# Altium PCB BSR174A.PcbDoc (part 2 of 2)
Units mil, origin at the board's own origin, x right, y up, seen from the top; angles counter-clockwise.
Board outline 4000 x 3000 mil, 6 copper layers (Top Layer, Signal Layer 1, Signal Layer 2, Signal Layer 3, Signal Layer 4, Bottom Layer), stack 61.8 mil thick; 80 components, 28 nets, 166 pads, 381 vias.
Unrouted connection lines stored in the file: 48.
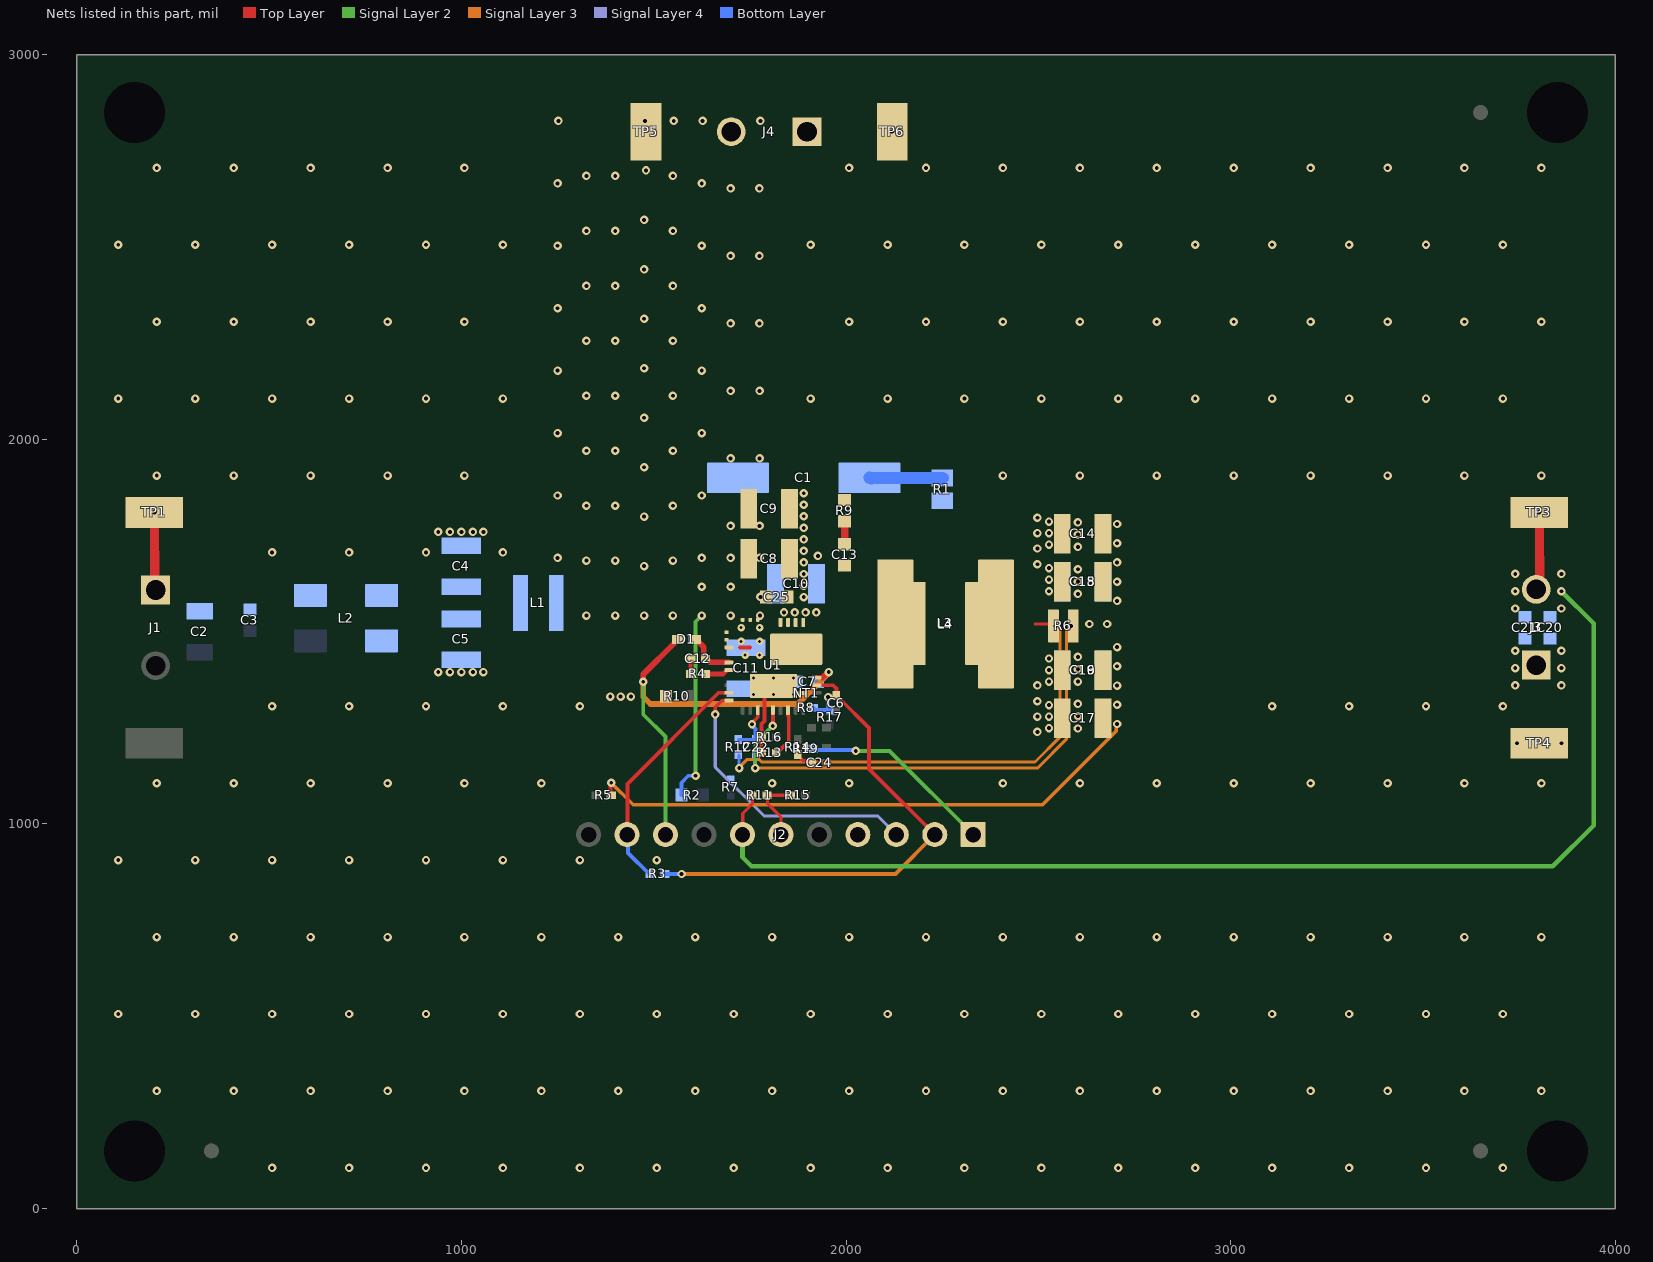
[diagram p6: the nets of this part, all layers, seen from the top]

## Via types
v1: diameter 22, hole 10, Top Layer to Bottom Layer, tented both sides, 364 vias
v2: diameter 19.68, hole 7.87, Top Layer to Bottom Layer, 12 vias
v3: diameter 22, hole 10, Top Layer to Bottom Layer, 5 vias

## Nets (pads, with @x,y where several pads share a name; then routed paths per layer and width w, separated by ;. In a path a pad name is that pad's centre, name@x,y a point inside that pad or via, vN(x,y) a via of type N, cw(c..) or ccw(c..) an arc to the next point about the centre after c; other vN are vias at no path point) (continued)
GND: C4.2 C5.2 C7.2 C8.2 C9.2 C10.2 C11.2 C14.2 C15.2 C16.2 C17.2 C18.2 C19.2 C20.2 C21.2 C25.2 J2.4 J3.1 J4.1 L2.2 NT1.1 R1.1 R7.1 R9.2 R10.1 R13.2 R16.1 TP4.1 TP6.1 U1.23 U1.24 U1.25 U1.26 U1.30 | length 199.3
  Top Layer w6: U1.30@1819.18,1343.22 U1.30@1828.28,1352.32
  Top Layer w10: R13.2@1780.31,1185 1780.32,1259.61 1788.5,1267.8 1788.5,1335.55 U1.30@1811.46,1358.5
  other v1: 508,106 708,106 908,106 1108,106 1308,106 1508,106 1708,106 1908,106 2108,106 2308,106 2508,106 2708,106 2908,106 3108,106 3308,106 3508,106 3708,106 208,306 408,306 608,306 808,306 1008,306 1208,306 1408,306 1608,306 1808,306 2008,306 2208,306 2408,306 2608,306 2808,306 3008,306 3208,306 3408,306 3608,306 3808,306 108,506 308,506 508,506 708,506 908,506 1108,506 1308,506 1508,506 1708,506 1908,506 2108,506 2308,506 2508,506 2708,506 2908,506 3108,506 3308,506 3508,506 3708,506 208,706 408,706 608,706 808,706 1008,706 1208,706 1408,706 1608,706 1808,706 2008,706 2208,706 2408,706 2608,706 2808,706 3008,706 3208,706 3408,706 3608,706 3808,706 108,906 308,906 508,906 708,906 908,906 1108,906 1308,906 1508,906 208,1106 408,1106 608,1106 808,1106 1008,1106 1208,1106 1808,1106 2008,1106 2408,1106 2608,1106 2808,1106 3008,1106 3208,1106 3408,1106 3608,1106 3808,1106 2497.81,1239.34 2602.81,1248.34 2527.81,1249.34 2497.81,1279.34 2527.81,1279.34 2603.2,1280.34 508,1306 708,1306 908,1306 1108,1306 1308,1306 3108,1306 3308,1306 3508,1306 3708,1306 2527.81,1309.34 2602.81,1312.34 2497.81,1319.34 1386.95,1331.4 1413.95,1331.4 1440.95,1331.4 2497.81,1360.34 3740,1360.34 3860,1360.34 2527.81,1370.34 2602.81,1370.34 940,1395 970,1395 1000,1395 1030,1395 1057.24,1395 2527.81,1400.34 2602.81,1402.34 3740,1405.34 3860,1405.34 2527.81,1430.34 2602.81,1434.34 3740,1450.34 3860,1450.34 1838.81,1550.34 1866.81,1550.34 1894.81,1550.34 1922.81,1550.34 1890,1590 2602.81,1598.36 2527.81,1605.34 1890,1620 2602.81,1630.35 2527.81,1635.34 1890,1650 2602.81,1662.34 2527.81,1665.34 2497.81,1675.34 1890,1680 1926.87,1697.24 508,1706 708,1706 908,1706 1108,1706 1890,1710 2497.81,1716.34 2602.81,1720.34 2527.81,1726.34 1890,1740 2602.81,1752.34 2497.81,1756.34 2527.81,1756.34 940,1759.3 970,1759.3 1000,1759.3 1030,1759.3 1057.24,1759.3 1890,1770 2602.81,1784.34 2527.81,1786.34 2497.81,1796.34 1890,1800 1890,1830 1890,1860 208,1906 408,1906 608,1906 808,1906 1008,1906 2408,1906 2608,1906 2808,1906 3008,1906 3208,1906 3408,1906 3608,1906 3808,1906 108,2106 308,2106 508,2106 708,2106 908,2106 1108,2106 1908,2106 2108,2106 2308,2106 2508,2106 2708,2106 2908,2106 3108,2106 3308,2106 3508,2106 3708,2106 208,2306 408,2306 608,2306 808,2306 1008,2306 2008,2306 2208,2306 2408,2306 2608,2306 2808,2306 3008,2306 3208,2306 3408,2306 3608,2306 3808,2306 108,2506 308,2506 508,2506 708,2506 908,2506 1108,2506 1908,2506 2108,2506 2308,2506 2508,2506 2708,2506 2908,2506 3108,2506 3308,2506 3508,2506 3708,2506 208,2706 408,2706 608,2706 808,2706 1008,2706 2008,2706 2208,2706 2408,2706 2608,2706 2808,2706 3008,2706 3208,2706 3408,2706 3608,2706 3808,2706 2120,2800
  other v2: 1759.8,1337.17 1811.46,1337.17 1863.15,1337.17 1759.8,1379.84 1811.46,1379.84 1863.15,1379.84
  other v3: 3745,1210 3860,1210
ISNS+: C22.2 R12.1 U1.11 | length 128.5
  Top Layer w10: v1(1755.57,1259.34) 1755.57,1262.59 1770.55,1277.58 1770.55,1295.75 U1.11@1770.63,1295.83
  Bottom Layer w10: R12.1@1721.46,1218.92 C22.2@1763.71,1218.92 ; v1(1755.57,1259.34) 1755.57,1256.1 1765,1246.66 C22.2@1765,1219.69
NetC1_2: C1.2 R1.2 | length 191.1
  Bottom Layer w32: C1.2@2061.26,1900 2061.5,1899.76 2250.37,1899.76 2250.97,1899.17 R1.2@2251.32,1899.53 ; C1.2@2066.07,1898.82 C1.2@2066.43,1899.17
NetC2_1: C2.1 C3.1 J1.1 L2.4 TP1.1 | length 201.2
  Top Layer w24: v3(202,1810) J1.1@202.81,1608.77
NetC4_1: C4.1 C5.1 L1.1 L2.1
NetC12_1: C12.1 D1.1 U1.4 | length 130.4
  Top Layer w12: U1.4@1695.22,1420.45 U1.4@1695.83,1419.84
  Top Layer w15: D1.1@1606.65,1480 1610.59,1480 1630.37,1460.22 1630.37,1432.34 1632.72,1430 C12.1@1634.68,1430 1636.65,1430 1646.2,1420.45 U1.4@1695.22,1420.45
NetC12_2: C12.2 R4.2 | length 40
  Top Layer w10: R4.2@1595.31,1390 C12.2@1595.31,1430
NetC13_2: C13.2 R9.1 | length 59.9
  Top Layer w20: C13.2@1996.45,1727.2 R9.1@1996.45,1787.13
NetC24_1: C24.1 R14.1 | length 41.7
  Top Layer w10: R14.1@1875.89,1177.46 1888.8,1164.55 1905.77,1164.55 C24.1@1910.32,1160
NetJ2_1: J2.1 R19.1 | length 511.2
  Top Layer w10: J2.1@2330.5,972.66 J2.1@2330.81,972.34
  Signal Layer 2 w10: v1(2025.16,1190) 2113.16,1190 J2.1@2330.81,972.34
  Bottom Layer w10: R19.1@1914.68,1199.84 1914.68,1199.11 1921.5,1192.3 2022.86,1192.3 v1(2025.16,1190)
NetL3_2: L3.2 L4.2 R6.1 R12.2 | length 1242.3
  Top Layer w8: v1@1721.46,1146.27 v1(1722.38,1145.34) ; 2492.03,1520.34 R6.1@2530,1520.42
  Signal Layer 3 w8: v1(1722.38,1145.34) 1722.38,1147.42 1743.19,1168.22 1773.59,1168.22 1780.59,1161.22 2491.25,1161.22 2556.94,1226.91 2556.94,1503.06 v1(2545,1515)
  Bottom Layer w8: R12.2@1721.46,1179.55 1721.46,1146.27 v1(1722.38,1145.34)
PFMSYNC: J2.3 U1.8 | length 742.4
  Top Layer w8: v1(1660,1285) 1660,1303.48 1677.94,1321.42 U1.8@1695.83,1321.42
  Signal Layer 4 w8: v1(1660,1285) 1660,1147.81 1786.74,1021.07 2082.08,1021.07 J2.3@2130.81,972.34
PGSYNC: J2.10 R3.1 U1.7 | length 622.2
  Top Layer w10: J2.10@1431.53,972.34 1431.53,1103.91 1668.73,1341.1 U1.7@1695.83,1341.1
  Bottom Layer w10: J2.10@1430.81,972.34 1433.48,969.68 1433.48,924.86 1488.35,870 R3.1@1490.32,870
RT: R13.1 U1.14 | length 121.3
  Top Layer w10: R13.1@1822.83,1187.44 1825.58,1190.19 1826.16,1190.19 1851.26,1215.29 1851.26,1280.76 1849.45,1282.57 1849.45,1295.75 U1.14@1849.37,1295.83
SW: C13.1 L3.1 L4.1 U1. U1.20 U1.21 U1.22
SW1: R4.1 U1.5 | length 59.1
  Top Layer w12: R4.1@1634.68,1390 1680.94,1390 U1.5@1690.02,1399.08
VBODE: J2.6 R11.1 R15.2 | length 195.1
  Top Layer w8: J2.6@1849.53,972.34 1831.53,972.34 1831.53,1017.34 1796.22,1052.66 1796.22,1074.79 R15.2@1856.2,1074.79
VCC: C7.1 D1.2 J2.9 U1.19 | length 1224.6
  Top Layer w12: U1.19@1924.86,1381.16 1939.12,1381.16
  Top Layer w15: v1(1472.96,1369.98) 1472.96,1389.62 1555.1,1471.75 1555.1,1475.69 1559.41,1480 D1.2@1563.35,1480 ; 1939.12,1381.16 1939.81,1381.16 1953.65,1395 v1(1955,1395)
  Signal Layer 2 w10: v1(1472.96,1369.98) 1472.96,1285.1 1530.49,1227.57 J2.9@1530.49,973.39
  Signal Layer 3 w15: v1(1472.96,1369.98) 1472.96,1330.5 1491.51,1311.95 1874.78,1311.95 1951.5,1388.67 1951.5,1389.61 1955,1393.11 v1(1955,1395)
  Bottom Layer w15: C7.1@1933.62,1362.23 1925.37,1370.47 1925.37,1371.59 1933.62,1379.84 1941.81,1379.84 1941.81,1380.46 1955,1393.65 v1(1955,1395)
VDDA: C6.2 J2.2 R3.2 R8.2 R17.2 U1.18 | length 1379.2
  Top Layer w10: U1.18@1924.25,1360.71 U1.18@1924.17,1360.79 1966.53,1360.79 1975,1352.32 C6.2@1975,1333.68 1973.16,1331.84 1955.19,1331.84 v1(1953.35,1330) ; C6.2@1975,1331.71 1979.84,1326.87 1982.3,1326.87 2060,1249.17 2060,1143.16 J2.2@2230.81,972.34
  Signal Layer 3 w10: v1(1572.44,870) 2128.47,870 J2.2@2230.81,972.34
  Bottom Layer w10: R3.2@1529.69,870 v1(1572.44,870) ; R8.2@1915.94,1301.73 1920.78,1296.89 1928.38,1296.89 1928.61,1296.66 R17.2@1958.21,1296.66 ; R17.2@1953.37,1301.73 1953.37,1309.3 ; 1953.35,1309.33 v1(1953.35,1330)
VIN: C1.1 C8.1 C9.1 C10.1 C11.1 C25.1 J4.2 L1.2 R2.2 TP5.1 U1.1 U1.2 U1.3 U1.27 U1.28 U1.29 | length 525.6
  Top Layer w10: 1724.38,1459.17 1750.33,1459.17
  Signal Layer 2 w10: v1(1608.97,1125.34) 1608.97,1525.82 v1(1625,1541.85)
  Bottom Layer w10: R2.2@1571.94,1075.34 1571.94,1107.31 1589.97,1125.34 v1(1608.97,1125.34)
  other v1: 1325,1541.85 1400,1541.85 1475,1541.85 1550,1541.85 1700,1541.85 1776.43,1541.85 1777.33,1590.59 1625,1616.85 1700,1616.85 1475,1670.45 1325,1684.74 1400,1684.74 1550,1684.74 1250,1691.85 1625,1691.85 1700,1691.85 1775.4,1691.85 1700,1775 1775.4,1775 1475,1799.06 1325,1827.64 1400,1827.64 1550,1827.64 1250,1854.14 1625,1854.14 1475,1927.66 1700,1950.48 1775.4,1950.48 1325,1970.53 1400,1970.53 1550,1970.53 1250,2016.43 1625,2016.43 1475,2056.27 1325,2113.43 1400,2113.43 1550,2113.43 1700,2125.97 1775.4,2125.97 1250,2178.73 1625,2178.73 1475,2184.87 1325,2256.32 1400,2256.32 1550,2256.32 1700,2301.45 1775,2301.45 1475,2313.48 1250,2341.02 1625,2341.02 1325,2399.21 1400,2399.21 1550,2399.21 1475,2442.08 1700,2476.93 1775,2476.93 1250,2503.31 1625,2503.31 1325,2542.11 1400,2542.11 1550,2542.11 1475,2570.69 1700,2652.41 1775,2652.41 1250,2665.6 1625,2665.6 1325,2685 1400,2685 1550,2685 1480,2699.29 1252.33,2827.9 1477.33,2827.9 1552.33,2827.9 1627.33,2827.9 1777.33,2827.9
  other v2: 1737.8,1438.9 1775.55,1438.9 1727.32,1474.65 1775.55,1474.65 1727.32,1510.39 1775.55,1510.39
VOUT: C14.1 C15.1 C16.1 C17.1 C18.1 C19.1 C20.1 C21.1 C22.1 J2.7 J3.2 R5.1 R6.2 R11.2 TP3.1 U1.12 | length 6107.1
  Top Layer w8: J2.7@1731.53,972.34 1731.53,1027.43 1756.85,1052.75 R11.2@1756.85,1074.79 ; TP3.1@3798.81,1789.34 TP3.1@3802.81,1785.34
  Top Layer w10: R5.1@1387.5,1075.4 1387.5,1105.38 v1(1389.47,1107.34) ; v1(1809.51,1255.05) 1809.92,1255.46 1809.92,1295.75 U1.12@1810,1295.83
  Top Layer w24: TP3.1@3802.81,1809.19 3802.89,1789.36 J3.2@3803.63,1605.15
  Signal Layer 2 w10: v1(1764.11,1145.34) 1764.11,1209.92 1809.24,1255.05 v1(1809.51,1255.05)
  Signal Layer 2 w12: J2.7@1730.81,972.34 1730.81,913.57 1754.39,890 3837.81,890 3944,996.19 3944,1521.34 v1(3860,1605.34)
  Signal Layer 3 w8: v1(1764.11,1145.34) 2497.83,1145.34 2572.81,1220.33 2572.81,1502.81 v1(2585,1515)
  Signal Layer 3 w10: v1(1389.47,1107.34) 1446.81,1050 2511.08,1050 2702.7,1241.62 2702.7,1257.7 v1(2705,1260) ; J2.7@1728.21,972.34 J2.7@1730.81,972.34
  Bottom Layer w8: v1(1764.11,1145.34) C22.1@1764.11,1179.96
  other v1: 2705,1310 2705,1360 2705,1410 2705,1460 2632.81,1520 2678.81,1520 3740,1560.34 3860,1560.34 2705,1580 3740,1605.34 2705,1630 3740,1650.34 3860,1650.34 2705,1680 2705,1730 2705,1780
  other v3: 3802,1810
pads on no net: FID1.1 FID2.1 FID3.1 FID4.1 FID5.1 FID6.1 MH1.1 MH2.1 MH3.1 MH4.1 U1.10

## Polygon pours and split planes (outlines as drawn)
SW on Top Layer "TOP_LAYER_SW_P3590" (solid, remove dead copper, pour order 3590): 1926.32,1410.61 1921.94,1406.23 cw(c1918.54,1409.62) 1918.54,1404.82 1806.18,1404.82 cw(c1806.18,1411.58) 1799.42,1411.58 1799.42,1492.75 cw(c1807.66,1492.76) 1807.68,1500.99 1909.15,1500.77 ccw(c1909.2,1522.43) 1924.5,1507.1 1965.25,1547.76 ccw(c1948.18,1564.87) 1972.36,1564.88 1972.36,1683.25 cw(c1982.27,1683.25) 1982.27,1693.17 2196.12,1693.17 cw(c2196.12,1682.55) 2206.74,1682.55 2206.74,1357.89 cw(c2199.05,1357.89) 2199.05,1350.2 2080.26,1350.2 cw(c2080.26,1378.05) 2060.56,1358.35 2022.25,1396.67 ccw(c1982.89,1357.32) 1982.87,1412.98 1932.04,1412.98 ccw(c1932.03,1404.9)
VIN on Top Layer "TOP_LAYER_VIN_P3592" (solid, remove dead copper, pour order 3592): 1656.5,1438.1 1656.5,1464.14 ccw(c1615.1,1464.14) 1614.92,1505.54 1250.98,1504.04 cw(c1250.89,1524.93) 1230,1524.93 1230,2831.22 cw(c1272.44,2831.22) 1272.44,2873.66 1772.09,2873.66 cw(c1772.09,2831.22) 1814.53,2831.21 1814.54,1566.88 1805.89,1566.88 ccw(c1805.89,1549.14) 1788.15,1549.14 1788.15,1427.68 1666.91,1427.68 cw(c1666.91,1438.1)
NetL3_2 on Top Layer "TOP_LAYER_NETL3_2_P3589" (solid, remove dead copper, pour order 3589): 2436.89,1648.98 2436.89,1688.34 ccw(c2432.06,1688.34) 2432.06,1693.17 2317.5,1693.17 ccw(c2317.5,1685.67) 2310,1685.67 2310,1577.49 2310,1490.94 2310,1354.73 ccw(c2314.54,1354.73) 2314.54,1350.2 2437.27,1350.2 ccw(c2437.27,1355.02) 2442.1,1355.02 2442.1,1393.43 cw(c2493.12,1393.43) 2457.04,1429.51 2481.71,1454.18 cw(c2514.88,1421.02) 2514.88,1467.92 2555,1467.92 2555,1566.66 2513.85,1566.66 cw(c2513.85,1609.41) 2483.62,1579.18 2453.2,1609.59 cw(c2492.58,1648.98)
GND on Top Layer "TOP_LAYER_GND_P3593" (solid, pour order 3593): -0.49,0 -0.49,3000 4000,3000 4000,0
AGND on Top Layer "TOP_LAYER_AGND_P3588" (solid, remove dead copper, pour order 3588): 1906.11,1345.66 1935.98,1345.66 1935.98,1320.08 ccw(c1946.3,1320.08) 1946.3,1309.76 1980.15,1309.76 cw(c1980.15,1305.69) 1984.23,1305.67 1983.51,1159.8 cw(c1973.68,1159.83) 1973.67,1150 1940,1150 cw(c1939.99,1156.18) 1933.81,1156.19 1933.81,1260.89 1906.11,1288.6
VOUT on Top Layer "TOP_LAYER_VOUT_P3591" (solid, remove dead copper, pour order 3591): 2642.59,1797.63 2642.59,1579.17 cw(c2621.75,1579.17) 2621.75,1558.33 2574.94,1558.33 2574.94,1471.79 2624.96,1471.79 cw(c2624.96,1454.16) 2642.59,1454.15 2642.59,1224.08 ccw(c2671.37,1224.08) 2671.37,1195.31 2766.61,1195.31 ccw(c2766.61,1218.7) 2790,1218.7 2790,1441.56 cw(c2820.23,1441.56) 2820.23,1471.79 3974.78,1471.79 3974.78,1689.19 2813.6,1689.19 cw(c2813.6,1712.8) 2790,1712.8 2790,1788.59 ccw(c2761.07,1788.59) 2761.07,1817.52 2662.49,1817.52 ccw(c2662.49,1797.63)
VOUT on Bottom Layer "BOTTOM_LAYER_VOUT_P3607" (solid, remove dead copper, pour order 3607): 2638.33,1788.03 2638.33,1580.62 cw(c2625.67,1580.62) 2625.67,1567.96 2616.21,1567.96 ccw(c2616.21,1556.14) 2604.4,1556.14 2604.4,1472.01 ccw(c2614.22,1472.01) 2614.22,1462.19 2629.85,1462.19 cw(c2629.85,1453.71) 2638.33,1453.71 2638.33,1223.77 ccw(c2666.79,1223.77) 2666.79,1195.31 2764.16,1195.31 ccw(c2764.16,1224.41) 2793.26,1224.41 2793.26,1469 cw(c2831.45,1469) 2831.45,1507.2 3873.29,1507.2 ccw(c3873.29,1526.66) 3892.75,1526.66 3892.75,1669.75 ccw(c3873.94,1669.76) 3873.93,1688.57 2822.86,1688.57 cw(c2822.86,1718.17) 2793.26,1718.18 2793.26,1787 ccw(c2759.25,1787) 2759.25,1821.01 2671.32,1821.01 ccw(c2671.31,1788.03)
GND on Bottom Layer "BOTTOM_LAYER_GND_P3609" (solid, remove dead copper, pour order 3609): -7,0 -7,3000 4000,3000 4000,0
NetC2_1 on Bottom Layer "BOTTOM_LAYER_NETC2_1_P3604" (solid, remove dead copper, pour order 3604): 877.81,1550 330,1550 330,1634.53 877.81,1634.53
EMIGND on Bottom Layer "BOTTOM_LAYER_EMIGND_P3602" (solid, remove dead copper, pour order 3602): 624.14,1411.57 330,1411.57 330,1486.14 cw(c352.56,1486.14) 352.56,1508.7 650,1508.7 650,1437.43 cw(c624.14,1437.43)
NetC4_1 on Bottom Layer "BOTTOM_LAYER_NETC4_1_P3603" (solid, remove dead copper, pour order 3603): 746,1639.76 1169.93,1639.76 1169.93,1512.05 746,1512.05
EMIGND on Bottom Layer "BOTTOM_LAYER_EMIGND_P3605" (solid, remove dead copper, pour order 3605): 2.38,1490 321.02,1490 cw(c321.02,1453.2) 357.81,1453.2 357.81,1217.81 cw(c325.34,1217.81) 325.34,1185.34 2.38,1185.34
NetC2_1 on Bottom Layer "BOTTOM_LAYER_NETC2_1_P3606" (solid, remove dead copper, pour order 3606): 2.38,1514.51 315.23,1514.51 ccw(c315.23,1557.09) 357.81,1557.09 357.81,1808.23 ccw(c330.7,1808.23) 330.7,1835.34 2.38,1835.34
VIN on Bottom Layer "BOTTOM_LAYER_VIN_P3608" (solid, remove dead copper, pour order 3608): 1837.24,3000 1837.24,1582.59 cw(c1821.2,1582.58) 1821.18,1566.54 1809.29,1566.54 ccw(c1809.28,1548.39) 1791.14,1548.38 1791.14,1438.03 cw(c1779.46,1438.02) 1779.45,1426.34 1258.17,1426.34 cw(c1258.17,1454.51) 1230,1454.51 1230,3000
VOUT on Signal Layer 2 "SIGNAL_LAYER_2_VOUT_P3596" (solid, remove dead copper, pour order 3596): 2638.08,1792.73 2638.08,1560.1 2604.37,1560.1 2604.37,1471.18 2638.08,1471.18 2638.08,1225.01 ccw(c2667.78,1225.01) 2667.78,1195.31 2771.52,1195.31 ccw(c2771.52,1218.04) 2794.25,1218.04 2794.25,1450.42 cw(c2815.01,1450.42) 2815.01,1471.18 3900,1471.18 3900,1687.98 2822.26,1687.98 cw(c2822.26,1715.99) 2794.25,1715.99 2794.25,1794.16 ccw(c2768.41,1794.16) 2768.41,1820 2665.35,1820 ccw(c2665.35,1792.73)
GND on Signal Layer 2 "SIGNAL_LAYER_2_GND_P3597" (solid, pour order 3597): 0,0 0,3000 4000,3000 4000,0
GND on Signal Layer 1 "SIGNAL_LAYER_1_GND_P3595" (solid, pour order 3595): 0,0 0,3000 4000,3000 4000,0
VOUT on Signal Layer 1 "SIGNAL_LAYER_1_VOUT_P3594" (solid, remove dead copper, pour order 3594): 3908.87,1520.56 3726.52,1520.56 cw(c3726.52,1542.09) 3704.99,1542.09 3704.99,1663.96 cw(c3726.52,1664.02) 3726.52,1685.56 3916.07,1685.56 cw(c3916.07,1657.62) 3944,1657.62 3944,1555.69 cw(c3908.87,1555.69)
VOUT on Signal Layer 3 "SIGNAL_LAYER_3_VOUT_P3598" (solid, remove dead copper, pour order 3598): 3928.96,1517.5 3730.37,1517.5 cw(c3730.37,1538.66) 3709.21,1538.66 3709.21,1659.34 cw(c3732.37,1659.34) 3732.37,1682.5 3930.7,1682.5 cw(c3930.7,1663.2) 3950,1663.2 3950,1538.54 cw(c3928.96,1538.54)
GND on Signal Layer 3 "SIGNAL_LAYER_3_GND_P3599" (solid, pour order 3599): 0,0 0,3000 4000,3000 4000,0
GND on Signal Layer 4 "SIGNAL_LAYER_4_GND_P3601" (solid, pour order 3601): 0,0 0,3000 4000,3000 4000,0
VOUT on Signal Layer 4 "SIGNAL_LAYER_4_VOUT_P3600" (solid, remove dead copper, pour order 3600): 3930.65,1520 3729.37,1520 cw(c3729.37,1539) 3710.37,1539 3710.37,1664 cw(c3731.37,1664) 3731.37,1685 3932.2,1685 cw(c3932.2,1667.2) 3950,1667.2 3950,1539.35 cw(c3930.65,1539.35)

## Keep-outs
Keep-Out Layer:
  lines w10: 0,1440 0,0 2270,0
  text ".Layer_Name" at 577,-818.49 h60

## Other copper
Top Layer:
  pour cut-out: 2206.74,1700.24 2206.74,1342.38 2310.82,1342.38 2310.81,1700.24
  pour cut-out: 2554.81,1561.3 2554.81,1468.41 2575.12,1468.41 2575.12,1561.3
  pour cut-out: 3708.07,1865 3708.07,1753.58 3889.56,1753.58 3889.56,1865
  pour cut-out: 1764.25,1240.4 1764.02,1173.34 1795.46,1173.34 1795.46,1240.33
  text ".Layer_Name" at 577,-818.49 h60
Signal Layer 1:
  pour cut-out: 2554.81,1561.3 2554.81,1468.41 2575.12,1468.41 2575.12,1561.3
  text ".layer_name" at 575,-815 h60
  text ".Layer_Name" at 580,-815 h60
Signal Layer 2:
  pour cut-out: 2554.81,1561.3 2554.81,1468.41 2575.12,1468.41 2575.12,1561.3
  text ".layer_name" at 575,-815 h60
  text ".Layer_Name" at 572.33,-817.49 h60
Signal Layer 3:
  pour cut-out: 2554.81,1561.3 2554.81,1468.41 2575.12,1468.41 2575.12,1561.3
  text ".Layer_Name" at 580,-820 h60
Signal Layer 4:
  pour cut-out: 2554.81,1561.3 2554.81,1468.41 2575.12,1468.41 2575.12,1561.3
  text ".Layer_Name" at 577,-812.49 h60
Bottom Layer:
  pour cut-out: 2554.81,1561.3 2554.81,1468.41 2575.12,1468.41 2575.12,1561.3
  pour cut-out: 65.49,1510 363.25,1510 363.25,1490 65.49,1490
  pour cut-out: 650,1400 650,1665 750,1665 750,1400
  pour cut-out: 1175,1500 1175,1650 1225,1650 1225,1500
  text ".Layer_Name" at 577,-818.49 h60
Multi-Layer:
  pour cut-out: 2585.27,1534.37 cw(c2585,1515) 2585,1495.63 cw(c2586.09,1513.94) 2567.78,1515.04 cw(c2586.04,1516.09)

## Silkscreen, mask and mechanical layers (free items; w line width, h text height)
Top Overlay:
  text "VIN+" at 1248.78,2870 h40
  text "VIN-" at 2207.13,2870 h40
  text "LM70880QEVM" at 2798.65,2620 h72.83
  text "'.PRJ_Number'.PCB_Rev" at 2798.65,2540 h72.83
  text "VIN_EMI+" at 90,1890 h45
  text "VOUT+" at 3740,1890 h45
  text "VIN_EMI-" at 90,1085 h45
  text "VOUT-" at 3740,1085 h45
  text "PG" at 1400.51,816.17 h45 r45
  text "EN" at 1600,816.17 h45 r45
  text "FB" at 1911.25,816.17 h45 r45
  text "VCC" at 1471.64,784.37 h45 r45
  text "GND" at 1977.78,784.37 h45 r45
  text "PFM" at 2080,784.37 h45 r45
  text "BIAS" at 1242.59,757.86 h45 r45
  text "VOUT" at 1643.52,752.56 h45 r45
  text "BODE" at 1745.42,752.56 h45 r45
  text "VDDA" at 2150,752.56 h45 r45
  text "COMP" at 2260,752.56 h45 r45
  text ".Layer_Name" at 577,-818.49 h60
Bottom Overlay:
  text "VIN+" at 264.81,1670.34 h40
  text "VOUT+" at 3907.81,1665.34 h40
  text "VIN-" at 264.81,1307.34 h40
  text "VOUT-" at 3907.81,1307.34 h40
  text ".Layer_Name" at 577,-818.49 h60
Top Paste:
  text ".Layer_Name" at 577,-818.49 h60
Bottom Paste:
  text ".Layer_Name" at 577,-818.49 h60
Top Solder:
  text ".Layer_Name" at 577,-818.49 h60
  text ".Layer_Name" at 577,-818.49 h60
Bottom Solder:
  text ".Layer_Name" at 577,-818.49 h60
Drill Guide:
  text ".Layer_Name" at 577,-818.49 h60
M1 Board Outline:
  lines w10: 0,0 0,3000 4000,3000 4000,0 0,0
  lines w47.24: 0,0 4000,0 4000,3000 0,3000 0,0
  text ".Layer_Name" at 577,-818.49 h60
M2 Board Dimensions:
  rectangle: 0,-235 125,-110
  rectangle: 125,-360 500,-235
  lines w7: 0,-235 1000,-235 ; 125,-360 125,-110 ; 250,-360 250,-110 ; 500,-360 500,-110 ; 750,-360 750,-110 ; 0,-360 1000,-360 1000,-110 0,-110 0,-360
  text ".Layer_Name" at 577,-818.49 h60
M3 3D STEP Top:
  text ".Layer_Name" at 577,-818.49 h60
M4 3D STEP Bottom:
  text ".Layer_Name" at 577,-818.49 h60
M5 Assembly Top:
  lines w10: -292,-890.17 6308,-890.17 ; -292,-686.83 6310,-686.83 ; -292,-483.5 -292,-1093.5 3713,-1093.5 6310,-1093.5 6310,-483.5 -291.5,-483.5 -291.5,-1093.5 1284,-1093.5 ; 2173,-1093.5 2173,-483.5 ; 3440,-686.83 3440,-483.5 ; 4280,-686.83 4280,-483.5 ; 4902,-1100 4902,-897.17
  text "COMPONENTS MARKED 'DNP' SHOULD NOT BE POPULATED." at 1153.5,-278.5 h60
  text "ASSEMBLY VARIANT:" at 1153,-394 h60
  text ".VariantName" at 2189,-394 h60
  text "PCB VIEWED FROM TOP SIDE" at -228.5,-615.67 h60
  text "BOARD #:" at 2248,-615.67 h60
  text ".PRJ_Number" at 2793.5,-615.67 h60
  text "REV:" at 3638,-615.67 h60
  text ".PCB_Rev" at 3929.5,-615.67 h60
  text "SVN REV:" at 4476,-615.67 h60
  text ".VersionControl_RevNumber" at 4982,-615.67 h60
  text "TID #:" at 2248,-819 h60
  text ".TID" at 2793.5,-819 h60
  text "PLOT NAME =" at -228.5,-1024.34 h60
  text ".plot_File_Name" at 577,-1024.34 h60
  text "GENERATED    :" at 2250,-1024.34 h60
  text ".Print_Date" at 3119.5,-1024.34 h60
  text ".Print_Time" at 3848.5,-1024.34 h60
  text "TEXAS INSTRUMENTS" at 5113,-1024.34 h60
M6 Assembly Bottom:
  lines w10: -292.5,-687.33 6309.5,-687.33 ; -290.5,-890.67 6309.5,-890.67 ; 1115.5,-1100.5 1115.5,-897.67 ; 1737.5,-687.33 1737.5,-484 ; 2577.5,-687.33 2577.5,-484 ; 3844.5,-1094 3844.5,-484 ; 4733.5,-1094 6309,-1094 6309,-484 -292.5,-484 -292.5,-1094 2304.5,-1094 6309.5,-1094 6309.5,-484
  text "COMPONENTS MARKED 'DNP' SHOULD NOT BE POPULATED." at 6102,-278 h60
  text ".VariantName" at 5058,-394 h60
  text "ASSEMBLY VARIANT:" at 6097,-394 h60
  text ".VersionControl_RevNumber" at 1035.5,-616.17 h60
  text "SVN REV:" at 1541.5,-616.17 h60
  text ".PCB_Rev" at 2088,-616.17 h60
  text "REV:" at 2379.5,-616.17 h60
  text ".PRJ_Number" at 3224,-616.17 h60
  text "BOARD #:" at 3769.5,-616.17 h60
  text "PCB VIEWED FROM BOTTOM SIDE" at 6246,-616.17 h60
  text ".TID" at 3224,-819.5 h60
  text "TID #:" at 3769.5,-819.5 h60
  text "TEXAS INSTRUMENTS" at 904.5,-1024.84 h60
  text ".Print_Time" at 2169,-1024.84 h60
  text ".Print_Date" at 2898,-1024.84 h60
  text "GENERATED    :" at 3767.5,-1024.84 h60
  text ".plot_File_Name" at 5440.5,-1024.84 h60
  text "PLOT NAME =" at 6246,-1024.84 h60
M9 Title Sheet:
  drawing of 57 lines, arcs and shapes, not listed
  text "1" at 739.84,8076.5 h70
  text "2" at 3235.5,8076.5 h70
  text "3" at 5724.84,8076.5 h70
  text "4" at 8231.51,8076.5 h70
  text "5" at 10730.5,8076.5 h70
  text "6" at 13235.5,8076.5 h70
  text "A" at -416.5,6933.5 h70
  text "A" at 14383.5,6933.5 h70
  text "B" at -416.5,4553.5 h70
  text "B" at 14383.5,4553.5 h70
  text "C" at -416.5,2178.5 h70
  text "C" at 14383.5,2178.5 h70
  text "PROJECT TITLE:" at 11343.5,317.5 h45
  text ".PRJ_Title" at 11393.5,184.17 h70
  text "DESIGNED FOR:" at 11343.5,16.5 h45
  text ".PRJ_Customer" at 11393.5,-123.5 h70
  text "D" at -416.5,-191.5 h70
  text "D" at 14383.5,-191.5 h70
  text "FILE NAME:" at 11343.5,-283.5 h45
  text ".PCB_File_Name_No_Path" at 11393.5,-403.5 h70
  text "Texas Instruments (TI) and/or its licensors do not warrant the accuracy or completeness of this specification" at 6374,-565.34 h45
  text "ENGINEER:" at 11343.5,-573.5 h45
  text "LAYOUT BY:" at 12848.5,-573.5 h45
  text "or any information contained therein. TI and/or its licensors do not warrant that this design will meet" at 6329.01,-678 h45
  text ".PRJ_Engineer" at 11393.5,-728.49 h70
  text ".PCB_Layout" at 12899,-728.49 h70
  text "the specifications, will be suitable for your application or fit for any particular purpose, or will operate in" at 6329.01,-790.67 h45
  text ".Layer_Name" at 577,-818.49 h60
  text "ALTIUM DESIGNER VERSION:" at 12848.5,-883.5 h45
  text "an implementation. TI and/or its licensors do not warrant that the design is production worthy. You should" at 6329.01,-903.33 h45
  text "completely validate and test your design implementation to confirm the system functionality for your application." at 6374,-1016 h45
  text ".print_Scale" at 11393.5,-1016.83 h70
  text ".Application_BuildNumber" at 12899,-1016.83 h70
  text "1" at 739.84,-1223.5 h70
  text "2" at 3235.5,-1223.5 h70
  text "3" at 5724.84,-1223.5 h70
  text "4" at 8231.51,-1223.5 h70
  text "5" at 10730.5,-1223.5 h70
  text "6" at 13235.5,-1223.5 h70
M10 Fab Notes:
  drawing of 189 lines, arcs and shapes, not listed
  text "DESIGN INFORMATION" at 12382.02,6396.17 h60
  text "MIN. TRACK WIDTH:" at 11737.46,6264.05 h60
  text "8" at 12833.7,6264.05 h60
  text "MIL" at 12988.46,6264.05 h60
  text "MIN. CLEARANCE:" at 11737.46,6139.92 h60
  text "0.2" at 12773.7,6139.93 h60
  text "mm" at 12988.46,6139.92 h60
  text "MIN. VIA PAD SIZE:" at 11737.46,6015.8 h60
  text "19.685" at 12630,6015.8 h60
  text "MIL" at 12988.46,6015.8 h60
  text "0.05mm (2MIL)" at 12432.46,5885.9 h60
  text "MINIMUM ANNULAR RING" at 11408.23,5877.67 h60
  text "EXTERNAL" at 13140.46,5877.67 h60
  text "PER" at 11608.23,5767.55 h60
  text "IPC-D-275 CLASS 2 LEVEL C" at 11828.23,5767.54 h60
  text "MIL, HOLES" at 13316.46,5667.07 h60
  text "+/-" at 12924,5658.48 h60
  text "+/-" at 13778,5658.48 h60
  text "REGISTRATION TOLERANCES:" at 11408.23,5657.42 h60
  text "METAL" at 12608,5657.42 h60
  text "5" at 13184.2,5657.42 h60
  text "3" at 14017.2,5657.42 h60
  text "MIL" at 14133.46,5657.42 h60
  text "HOLE SIZE TOLERANCE (UNLESS OTHERWISE SPECIFIED):" at 11408.23,5559.1 h60
  text "+/-" at 13778,5556.23 h60
  text "3" at 14017.2,5555.17 h60
  text "MIL" at 14133.46,5555.17 h60
  text "MATERIAL:" at 11333.46,5417.52 h60
  text "FR-4 High Tg" at 12319.9,5289 h60
  text "X" at 12175.46,5281.01 h60
  text "FR-408" at 11754.46,5276.49 h60
  text "OTHER" at 13242.46,5276.49 h60
  text "62 MIL (1.6mm) +/-10%" at 12074.56,5133.46 h60
  text "X" at 11954.46,5131.01 h60
  text "THICKNESS:" at 11408.23,5125.24 h60
  text "OTHER" at 13359.46,5125.24 h60
  text "TOLERANCE:" at 11408.23,4986.92 h60
  text "X" at 12256.46,4986.92 h60
  text "ANSI IPC-6012 TYPE 3 CLASS 2" at 12434.48,4986.92 h60
  text "OTHER +/-" at 12434.46,4842.73 h60
  text "BOW & TWIST:" at 11408.23,4697.54 h60
  text "X" at 12256.46,4697.54 h60
  text "ANSI IPC-6012 TYPE 3 CLASS 2" at 12434.48,4697.54 h60
  text "OTHER +/-" at 12434.46,4550.85 h60
  text "DRILLING:" at 11333.46,4420.23 h60
  text "NC_DRILL FILES" at 13094.46,4315.04 h60
  text "REFERENCE:" at 11408.23,4311.1 h60
  text "X" at 12065.46,4311.01 h60
  text "AS SHOWN" at 12243.46,4311.1 h60
  text "X" at 12966.46,4311.1 h60
  text "OTHER" at 13392.46,4168.85 h60
  text "PTH COPPER THICKNESS:" at 11407.91,4165.32 h60
  text "X" at 12547.14,4165.32 h60
  text "20-30 um" at 12675.14,4165.32 h60
  text "BOARD FINISH:" at 11333.46,4017.73 h60
  text "SILKSCREEN:" at 11488.68,3907.6 h60
  text "X" at 12446.46,3907.6 h60
  text "TOP" at 12563.46,3907.6 h60
  text "X" at 12956.46,3907.6 h60
  text "BOTTOM" at 13074.46,3907.6 h60
  text "SILKSCREEN COLOR:" at 11488.68,3752.41 h60
  text "X" at 12445.46,3752.41 h60
  text "WHITE" at 12563.46,3752.41 h60
  text "OTHER" at 13074.46,3752.41 h60
  text "X" at 12576.46,3608.96 h60
  text "GREEN" at 12694.46,3608.96 h60
  text "OTHER" at 13312.46,3608.96 h60
  text "SOLDER RESIST COLOR:" at 11488.68,3602.1 h60
  text "X" at 12576.46,3454.71 h60
  text "MATTE" at 12694.46,3454.71 h60
  text "SEMI-GLOSS" at 13312,3454.07 h60
  text "IMMERSION GOLD (ENIG)" at 12394.46,3281.94 h60
  text "ENEPIG" at 13732,3274.72 h60
  text "SURFACE FINISH:" at 11333.46,3273.72 h60
  text "X" at 12216.46,3273.72 h60
  text "IMM. TIN/SILVER OR EQUIV" at 11663,3136.4 h60
  text "OTHER" at 13094.46,3132.47 h60
  text "ARRAY/PANEL:" at 11333.46,2977.09 h60
  text "CUT AND TRIM PER M1 BOARD OUTLINE" at 12394.46,2968.87 h60
  text "N.C. ROUTE" at 12394.46,2832.9 h60
  text "X" at 13082.46,2832.9 h60
  text "V. SCORE" at 13260.46,2832.9 h60
  text "CERTIFICATION:" at 11333.46,2703.77 h60
  text "MATERIALS AND WORKMANSHIP FOR ALL PCBS" at 12058.46,2703.77 h60
  text "TO MEET OR EXCEED THE REQUIREMENTS OF:" at 12058.46,2609.71 h60
  text "X" at 11695.97,2481.08 h60
  text "ANSI IPC-A-600F CLASS ->" at 11823.96,2481.08 h60
  text "X" at 13471.97,2481.08 h60
  text "2" at 13581.96,2481.08 h60
  text "1" at 13266.96,2479.58 h60
  text "3" at 13935.96,2479.58 h60
  text "X" at 12507.97,2333.39 h60
  text "RoHS" at 12635.96,2333.39 h60
  text "OTHER" at 13280.36,2333.39 h60
  text "PER ORDER" at 13677.42,2333.39 h60
  text "ALL BOARDS MUST MEET OR EXCEED UL94-V0 REQUIREMENTS." at 11361,2179.57 h60
  text "PCB MUST BEAR THE UL94V-0 UL REGISTERED MATERIAL ID NUMBER" at 11361,2063.5 h60
  text "ADDITIONAL REQUIREMENTS:" at 11333.46,1894.08 h60
  text "MICROSECTION:" at 11408.23,1786.95 h60
  text "YES" at 12313.96,1786.95 h60
  text "REQUIRED" at 13175.46,1642.62 h60
  text "BARE BOARD ELEC. TEST:" at 11408.23,1639.76 h60
  text "NONE" at 12713.96,1639.76 h60
  text "X" at 13057.46,1639.76 h60
  text "PER ORDER" at 13767.46,1639.76 h60
  text "XX MIL VIAS REQUIRE NON-CONDUCTIVE FILL AND PLANARIZE" at 11576.38,1434.82 h59
  text "XX MIL VIAS REQUIRE CONDUCTIVE FILL AND PLANARIZE" at 11584.38,1330.84 h60
  text "OUTER XX MIL TRACES REQUIRE 50 OHM SINGLE-ENDED IMPEDANCE" at 11583.39,1167.46 h58
  text "LAYER 2 & 3 (INNER LAYERS) XX MIL WIDE, XX MIL SPACE / TRACES REQUIRE 100 OHM DIFFERENTIAL IMPEDANCE" at 11575.39,931.74 h60
  text ".Layer_Name" at 577,-818.49 h60
M11 Gerber Information:
  lines w10: -292,-890.17 6308,-890.17 ; -292,-686.83 6310,-686.83 ; -292,-483.5 -292,-1093.5 3713,-1093.5 6310,-1093.5 6310,-483.5 -291.5,-483.5 -291.5,-1093.5 1284,-1093.5 ; 2173,-1093.5 2173,-483.5 ; 3440,-686.83 3440,-483.5 ; 4280,-686.83 4280,-483.5 ; 4902,-1100 4902,-897.17
  text "ALL ARTWORK VIEWED FROM TOP SIDE" at -228.5,-615.67 h60
  text "BOARD #:" at 2248,-615.67 h60
  text ".PRJ_Number" at 2793.5,-615.67 h60
  text "REV:" at 3638,-615.67 h60
  text ".PCB_Rev" at 3929.5,-615.67 h60
  text "SVN REV:" at 4476,-615.67 h60
  text ".VersionControl_RevNumber" at 4982,-615.67 h60
  text "LAYER NAME =" at -228.5,-818.49 h60
  text "TID #:" at 2248,-819 h60
  text ".TID" at 2793.5,-819 h60
  text "PLOT NAME =" at -228.5,-1024.34 h60
  text ".plot_File_Name" at 577,-1024.34 h60
  text "GENERATED    :" at 2250,-1024.34 h60
  text ".Print_Date" at 3119.5,-1024.34 h60
  text ".Print_Time" at 3848.5,-1024.34 h60
  text "TEXAS INSTRUMENTS" at 5113,-1024.34 h60
M12 Stackup:
  drawing of 399 lines, arcs and shapes, not listed
  text "Layer" at 6690.58,7090 h60
  text "Name" at 7100.49,7090 h60
  text "Material" at 8040.23,7090 h60
  text "Thickness" at 8900,7090 h60
  text "Constant" at 9549.84,7090 h60
  text "Board Layer Stack" at 10119.7,7090 h60
  text "Top Overlay" at 7100.49,6970 h60
  text "Top Solder" at 7100.49,6850 h60
  text "Solder Resist" at 8040.23,6850 h60
  text "0.40mil" at 8900,6850 h60
  text "3.5" at 9549.84,6850 h60
  text "1" at 6690.58,6730 h60
  text "Top Layer" at 7100.49,6730 h60
  text "2.80mil" at 8900,6730 h60
  text "Dielectric1" at 7100.49,6610 h60
  text "FR4 Hi Tg" at 8040.23,6610 h60
  text "9.00mil" at 8900,6610 h60
  text "4.8" at 9549.84,6610 h60
  text "2" at 6690.58,6490 h60
  text "Signal Layer 1" at 7100.49,6490 h60
  text "2.80mil" at 8900,6490 h60
  text "Dielectric 2" at 7100.49,6370 h60
  text "FR4 Hi Tg" at 8040.23,6370 h60
  text "9.00mil" at 8900,6370 h60
  text "4.2" at 9549.84,6370 h60
  text "3" at 6690.58,6250 h60
  text "Signal Layer 2" at 7100.49,6250 h60
  text "2.80mil" at 8900,6250 h60
  text "Dielectric 3" at 7100.49,6130 h60
  text "FR4 Hi Tg" at 8040.23,6130 h60
  text "9.00mil" at 8900,6130 h60
  text "4.2" at 9549.84,6130 h60
  text "4" at 6690.58,6010 h60
  text "Signal Layer 3" at 7100.49,6010 h60
  text "2.80mil" at 8900,6010 h60
  text "Dielectric 4" at 7100.49,5890 h60
  text "FR4 Hi Tg" at 8040.23,5890 h60
  text "9.00mil" at 8900,5890 h60
  text "4.2" at 9549.84,5890 h60
  text "5" at 6690.58,5770 h60
  text "Signal Layer 4" at 7100.49,5770 h60
  text "2.80mil" at 8900,5770 h60
  text "Dielectric 5" at 7100.49,5650 h60
  text "FR4 Hi Tg" at 8040.23,5650 h60
  text "9.00mil" at 8900,5650 h60
  text "4.2" at 9549.84,5650 h60
  text "6" at 6690.58,5530 h60
  text "Bottom Layer" at 7100.49,5530 h60
  text "2.80mil" at 8900,5530 h60
  text "Bottom Solder" at 7100.49,5410 h60
  text "Solder Resist" at 8040.23,5410 h60
  text "0.40mil" at 8900,5410 h60
  text "3.5" at 9549.84,5410 h60
  text "Bottom Overlay" at 7100.49,5290 h60
  text "Total board thickness:" at 6690.58,5170 h60
  text "62.60mil" at 8900,5170 h60
  text ".Layer_Name" at 577,-818.49 h60
M13 Component Bodies Top:
  text ".Layer_Name" at 577,-818.49 h60
M14 Component Bodies Bottom:
  text ".Layer_Name" at 577,-818.49 h60
M15 Courtyards Top:
  text ".Layer_Name" at 577,-818.49 h60
M16 Courtyards Bottom:
  text ".Layer_Name" at 577,-818.49 h60
Drill Drawing:
  circle w10: c7934,4466.91 r27.63
  lines w10: 7906.37,4080.13 7920.18,4080.13 7934,4066.32 7947.81,4080.13 7961.62,4080.13 7947.81,4093.95 7961.62,4107.76 7947.81,4107.76 7934,4121.57 7920.18,4107.76 7906.37,4107.76 7920.18,4093.95 7906.37,4080.13 ; 7906.37,4245.89 7961.62,4245.89 7934,4190.64 7906.37,4245.89 ; 7906.37,4314.96 7934,4328.77 7961.62,4314.96 7947.81,4342.59 7961.62,4370.21 7934,4356.4 7906.37,4370.21 7920.18,4342.59 7906.37,4314.96 ; 7906.37,4563.6 7961.62,4563.6 7961.62,4618.85 7906.37,4618.85 7906.37,4563.6
  lines w12: 7856.28,4029.02 11087.77,4029.02 ; 7856.28,4650.62 11087.77,4650.62 ; 8194.14,3904.7 8194.14,4774.94 ; 8526.14,3904.7 8526.14,4774.94 ; 9162.7,3904.7 9162.7,4774.94 ; 9421.84,3904.7 9421.84,4774.94 ; 9797,3904.7 9797,4774.94 ; 10521.33,3904.7 10521.33,4774.94 ; 7856.28,3904.7 11087.77,3904.7 11087.77,4774.94 7856.28,4774.94 7856.28,3904.7
  text "Symbol" at 7930.87,4687.92 h72
  text "Quantity" at 8231.44,4687.92 h72
  text "Finished Hole Size" at 8563.44,4687.92 h72
  text "Plated" at 9200,4687.92 h72
  text "Hole Type" at 9459.14,4687.92 h72
  text "Drill Layer Pair" at 9834.3,4687.92 h72
  text "Hole Tolerance" at 10558.63,4687.92 h72
  text "4" at 8231.44,4563.6 h60
  text "159.00mil (4.039mm)" at 8563.44,4563.6 h60
  text "NPTH" at 9200,4563.6 h60
  text "Round" at 9459.14,4563.6 h60
  text "Top Layer - Bottom Layer" at 9834.3,4563.6 h60
  text "12" at 8231.44,4439.28 h60
  text "7.87mil (0.200mm)" at 8563.44,4439.28 h60
  text "PTH" at 9200,4439.28 h60
  text "Round" at 9459.14,4439.28 h60
  text "Top Layer - Bottom Layer" at 9834.3,4439.28 h60
  text "369" at 8231.44,4314.96 h60
  text "10.00mil (0.254mm)" at 8563.44,4314.96 h60
  text "PTH" at 9200,4314.96 h60
  text "Round" at 9459.14,4314.96 h60
  text "Top Layer - Bottom Layer" at 9834.3,4314.96 h60
  text "11" at 8231.44,4190.64 h60
  text "40.00mil (1.016mm)" at 8563.44,4190.64 h60
  text "PTH" at 9200,4190.64 h60
  text "Round" at 9459.14,4190.64 h60
  text "Top Layer - Bottom Layer" at 9834.3,4190.64 h60
  text "6" at 8231.44,4066.32 h60
  text "51.18mil (1.300mm)" at 8563.44,4066.32 h60
  text "PTH" at 9200,4066.32 h60
  text "Round" at 9459.14,4066.32 h60
  text "Top Layer - Bottom Layer" at 9834.3,4066.32 h60
  text "402 Total" at 8231.44,3942 h60
  text ".Layer_Name" at 577,-818.49 h60
M17 Embedded Cavity:
  text ".Layer_Name" at 577,-818.49 h60
M18 Embedded Assembly:
  text ".Layer_Name" at 577,-818.49 h60
M19 Embedded Keepout:
  text ".Layer_Name" at 577,-818.49 h60

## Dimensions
0,3000 to 0,0 on M2 Board Dimensions
0,-360 to 1000,-360 on M2 Board Dimensions
0,40 to 4000,0 on M2 Board Dimensions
